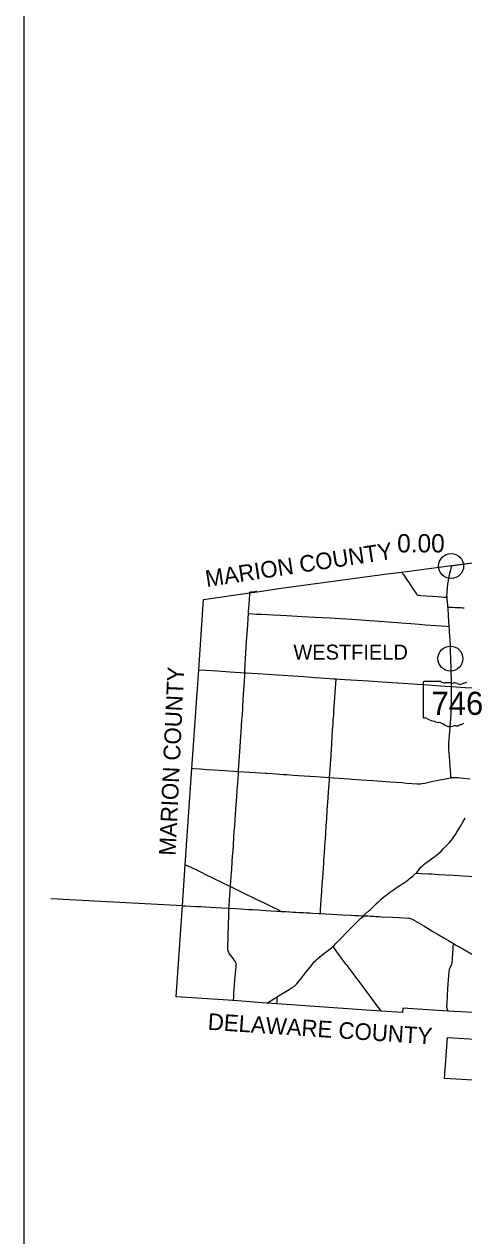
# Model space of a CAD drawing. Extents: x 1813937 to 1948437, y 826606 to 1022856.
# Drawn here: x 1813937 to 1840375, y 867056 to 939932 of the extents above; entities that cross this region are included whole.
import ezdxf

# ---------------------------------------------------------------- set-up
doc = ezdxf.new("R2010")
doc.units = 0
for name, color, linetype in [('Default', 7, 'Continuous'), ('GM_X_Adjacent_County', 7, 'Continuous'), ('GM_X_Adjacent_County_Text', 7, 'Continuous'), ('GM_X_Corporation', 7, 'Continuous'), ('GM_X_County', 7, 'Continuous'), ('GM_X_County_Road', 7, 'Continuous'), ('GM_X_State_Route', 7, 'Continuous'), ('GM_X_State_Shield', 7, 'Continuous'), ('GM_X_Township_Road', 7, 'Continuous'), ('GM_X_Township_Text', 7, 'Continuous'), ('SC_Scratch1', 7, 'Continuous')]:
    doc.layers.add(name, color=color, linetype=linetype)

msp = doc.modelspace()

# ---------------------------------------------------------------- linework, layer by layer
at = {"layer": 'Default'}
for centre in [(1839615, 907340), (1839615, 907340), (1839569, 901772)]:
    msp.add_circle(centre, 750, dxfattribs=at)
at = {"layer": 'GM_X_Adjacent_County'}
msp.add_line((1823458, 886911), (1815539, 887318), dxfattribs=at)
at = {"layer": 'GM_X_Corporation'}
msp.add_lwpolyline([(1840914, 876421), (1839212, 876522), (1839395, 878979), (1842403, 878797)], dxfattribs=at)
at = {"layer": 'GM_X_County'}
msp.add_lwpolyline([(1842150, 880416), (1839410, 880574), (1836708, 880754), (1836682, 880495), (1835395, 880574), (1829123, 881005), (1828513, 881052), (1826517, 881205), (1823082, 881429), (1823458, 886911), (1823627, 889370), (1824025, 895167), (1824431, 901093), (1824723, 905333), (1827503, 905733), (1827940, 905796), (1829401, 906007), (1835631, 906848), (1836624, 906977), (1839634, 907367), (1840896, 907530)], dxfattribs=at)
at = {"layer": 'GM_X_County_Road'}
for points in [[(1839641, 907367), (1839743, 907381), (1840149, 907433), (1840782, 907511), (1840900, 907526)], [(1836640, 906953), (1836662, 906929), (1836693, 906891), (1836740, 906824), (1836905, 906580), (1837062, 906349), (1837146, 906228), (1837275, 906038), (1837375, 905888), (1837508, 905681), (1837527, 905655), (1837538, 905643), (1837550, 905632), (1837563, 905622), (1837577, 905613), (1837592, 905607), (1837608, 905602), (1837640, 905594), (1837689, 905588), (1837786, 905579), (1838113, 905555), (1838489, 905526), (1838800, 905503), (1839012, 905486), (1839176, 905473), (1839290, 905464), (1839339, 905462), (1839367, 905462)], [(1827427, 904481), (1827436, 904614), (1827477, 905285), (1827502, 905699), (1827503, 905715), (1827505, 905729)], [(1827505, 905729), (1827509, 905742), (1827514, 905753), (1827521, 905760), (1827528, 905766), (1827537, 905772), (1827553, 905778), (1827569, 905783), (1827589, 905785), (1827635, 905791), (1827781, 905804), (1827829, 905810), (1827860, 905815), (1827876, 905820), (1827889, 905826), (1827901, 905834), (1827910, 905844)], [(1827209, 900922), (1827209, 900929), (1827211, 901011), (1827236, 901470), (1827252, 901764), (1827314, 902796), (1827379, 903779), (1827408, 904188), (1827427, 904481)], [(1839424, 904857), (1839445, 904858), (1839474, 904860), (1839506, 904861), (1839573, 904860), (1839703, 904858), (1839867, 904853), (1840015, 904847), (1840195, 904840), (1840326, 904836), (1840408, 904832)], [(1824436, 901107), (1824857, 901077), (1825561, 901032), (1826298, 900984), (1826625, 900961), (1826969, 900938), (1827209, 900922)], [(1826827, 894987), (1826827, 895001), (1826851, 895345), (1826907, 896163), (1826952, 896835), (1826990, 897375), (1827034, 898063), (1827056, 898390), (1827082, 898783), (1827090, 898914), (1827110, 899258), (1827135, 899684), (1827164, 900142), (1827200, 900716), (1827209, 900922)], [(1827209, 900922), (1827280, 900917), (1827984, 900871), (1829162, 900793), (1830734, 900688), (1831437, 900640), (1831765, 900619), (1832567, 900564), (1832693, 900555)], [(1832693, 900555), (1832927, 900540), (1833221, 900520), (1834662, 900428), (1835464, 900375), (1836413, 900311), (1837608, 900230), (1837903, 900211), (1838230, 900188), (1838983, 900135), (1839261, 900118), (1839621, 900093), (1839646, 900091)], [(1824029, 895174), (1824145, 895166), (1824536, 895137), (1824929, 895108), (1825305, 895085), (1826010, 895043), (1826550, 895005), (1826827, 894987)], [(1826343, 888063), (1826370, 888438), (1826380, 888568), (1826392, 888715), (1826419, 889075), (1826454, 889567), (1826474, 889861), (1826500, 890238), (1826520, 890532), (1826554, 891073), (1826572, 891351), (1826597, 891695), (1826625, 892087), (1826688, 892988), (1826719, 893430), (1826751, 893888), (1826777, 894264), (1826817, 894821), (1826827, 894987)], [(1826827, 894987), (1827156, 894965), (1827506, 894942)], [(1827506, 894942), (1828155, 894900), (1828455, 894881)], [(1828455, 894881), (1828532, 894877), (1828859, 894855), (1829530, 894810), (1829727, 894798), (1830120, 894771), (1830431, 894749), (1831462, 894677), (1832301, 894618)], [(1832301, 894618), (1832559, 894602), (1833475, 894538), (1833688, 894522), (1834196, 894488), (1834899, 894439), (1835177, 894417), (1835947, 894363), (1836650, 894312), (1836945, 894290), (1837567, 894246), (1837698, 894242), (1837781, 894246), (1837879, 894258), (1838024, 894284), (1838520, 894400), (1838728, 894446), (1838921, 894481), (1839196, 894528), (1839471, 894575), (1839625, 894604), (1839631, 894605)], [(1837518, 888876), (1837551, 888917), (1837744, 889159), (1837799, 889220), (1837903, 889325), (1837988, 889402), (1838065, 889464), (1838264, 889608), (1838521, 889784), (1838642, 889869), (1838731, 889941), (1838854, 890049), (1839010, 890195), (1839158, 890347), (1839507, 890717), (1839630, 890845), (1839695, 890924), (1839778, 891045), (1839879, 891194), (1839966, 891333), (1840066, 891502), (1840183, 891699), (1840348, 891983), (1840455, 892167)], [(1834737, 886671), (1834904, 886828), (1835023, 886940), (1835130, 887042), (1835261, 887166), (1835407, 887298), (1835568, 887438), (1835710, 887550), (1835908, 887695), (1836201, 887906), (1836376, 888028), (1836527, 888127), (1836707, 888242), (1836815, 888315), (1836921, 888392), (1837065, 888501), (1837181, 888592), (1837309, 888694), (1837421, 888783), (1837481, 888840), (1837518, 888876)], [(1837518, 888876), (1837545, 888874), (1837806, 888855), (1838261, 888836), (1838474, 888821), (1838867, 888795), (1839292, 888768), (1839784, 888737), (1840078, 888719), (1840275, 888709), (1840684, 888683), (1841175, 888655), (1841388, 888641), (1841830, 888620), (1842158, 888602), (1842612, 888567)], [(1826250, 886755), (1826256, 886850), (1826289, 887292), (1826303, 887521), (1826329, 887865), (1826343, 888063)], [(1826518, 881195), (1826536, 881422), (1826551, 881618), (1826574, 881929), (1826628, 882632), (1826662, 883058), (1826675, 883221), (1826686, 883334), (1826684, 883399), (1826678, 883441), (1826667, 883473), (1826659, 883494), (1826636, 883539), (1826590, 883612), (1826459, 883789), (1826348, 883931), (1826301, 883997), (1826268, 884054), (1826235, 884128), (1826207, 884204), (1826190, 884267), (1826183, 884314), (1826182, 884379), (1826191, 884592), (1826198, 884788), (1826200, 884821), (1826199, 884853), (1826200, 884902), (1826206, 885116), (1826212, 885312), (1826215, 885476), (1826221, 885735), (1826237, 886326), (1826250, 886755)], [(1826250, 886755), (1826282, 886753), (1826642, 886732), (1826970, 886714), (1827445, 886689), (1827658, 886677), (1828002, 886656), (1828461, 886630), (1829384, 886569)], [(1829384, 886569), (1829466, 886561), (1829676, 886552), (1829903, 886537), (1830116, 886527), (1830278, 886518), (1830475, 886508), (1830736, 886493), (1830931, 886483), (1831099, 886472), (1831295, 886460), (1831656, 886441), (1831744, 886436)], [(1831744, 886436), (1832062, 886419), (1832440, 886396), (1833047, 886365), (1833562, 886340), (1833797, 886327), (1834032, 886316), (1834242, 886307), (1834353, 886304)], [(1832502, 884457), (1832576, 884525), (1832678, 884631), (1832906, 884865), (1833078, 885042), (1833250, 885217), (1833397, 885371), (1833685, 885663), (1833837, 885813), (1833991, 885960), (1834109, 886073), (1834193, 886152), (1834335, 886287), (1834353, 886304)], [(1834353, 886304), (1834513, 886458), (1834678, 886615), (1834737, 886671)], [(1834353, 886304), (1834383, 886301), (1834407, 886298), (1834438, 886296), (1834628, 886291), (1834761, 886284), (1834849, 886280), (1834921, 886275)], [(1834921, 886275), (1834961, 886273), (1835065, 886268), (1835206, 886261), (1835289, 886256), (1835418, 886248), (1836089, 886214), (1836498, 886192), (1836760, 886178), (1837055, 886163), (1837120, 886156), (1837169, 886145), (1837216, 886130), (1837276, 886101), (1837967, 885691), (1838515, 885365), (1838829, 885180), (1839168, 884983), (1839465, 884807), (1839753, 884634)], [(1829163, 881447), (1829223, 881484), (1829868, 881877), (1830063, 881997), (1830187, 882077), (1830227, 882105), (1830275, 882149), (1830330, 882209), (1830475, 882386), (1830710, 882682), (1830923, 882952), (1831137, 883222), (1831331, 883466), (1831406, 883553), (1831475, 883623), (1831560, 883701), (1831700, 883815), (1831942, 884008), (1832417, 884385), (1832502, 884457)], [(1839429, 880574), (1839381, 880732), (1839365, 880796), (1839361, 880827), (1839361, 880876), (1839370, 881056), (1839423, 881923), (1839457, 882480), (1839475, 882709), (1839502, 882953), (1839513, 883035), (1839518, 883070), (1839526, 883110), (1839539, 883145), (1839552, 883173), (1839636, 883353), (1839660, 883414), (1839673, 883462), (1839684, 883527), (1839693, 883658), (1839721, 884067), (1839736, 884312), (1839746, 884506), (1839751, 884583), (1839753, 884634)], [(1839753, 884634), (1839900, 884546), (1840313, 884307), (1841735, 883496), (1842075, 883304), (1842113, 883283), (1842148, 883267), (1842176, 883258), (1842206, 883252), (1842265, 883243), (1842304, 883240), (1842349, 883237)], [(1828526, 881056), (1828986, 881338), (1829163, 881447)]]:
    msp.add_lwpolyline(points, dxfattribs=at)
at = {"layer": 'GM_X_State_Route'}
for points in [[(1839619, 894616), (1839616, 894620), (1839611, 894630), (1839608, 894643), (1839606, 894660), (1839600, 894774), (1839578, 895052), (1839536, 895559), (1839509, 895902), (1839492, 896115), (1839481, 896262), (1839474, 896409), (1839471, 896524), (1839473, 896606), (1839477, 896688), (1839495, 896901), (1839518, 897146), (1839541, 897407), (1839564, 897668), (1839577, 897848), (1839599, 898192), (1839616, 898470), (1839625, 898634), (1839635, 898896), (1839639, 899093), (1839642, 899306), (1839645, 899552), (1839646, 899879), (1839647, 900076), (1839646, 900091), (1839642, 900273), (1839638, 900437), (1839630, 900666), (1839624, 900879), (1839617, 901092), (1839611, 901305), (1839601, 901617), (1839594, 901797), (1839583, 902158), (1839577, 902371), (1839569, 902600), (1839553, 902944), (1839541, 903140), (1839526, 903369), (1839508, 903631), (1839503, 903706), (1839481, 904024), (1839459, 904367), (1839449, 904514), (1839438, 904662), (1839428, 904809), (1839424, 904857), (1839420, 904907), (1839407, 905037), (1839395, 905151), (1839374, 905363), (1839367, 905462), (1839367, 905469), (1839364, 905527), (1839365, 905610), (1839368, 905692), (1839375, 905790), (1839394, 906002), (1839421, 906263), (1839434, 906361), (1839453, 906474), (1839478, 906603), (1839525, 906828), (1839589, 907116), (1839629, 907309), (1839641, 907367)], [(1840732, 894516), (1840357, 894561), (1840162, 894586), (1840032, 894601), (1839967, 894607), (1839902, 894609), (1839836, 894607), (1839672, 894597), (1839660, 894597), (1839648, 894599), (1839638, 894601), (1839631, 894605), (1839623, 894611), (1839619, 894616)]]:
    msp.add_lwpolyline(points, dxfattribs=at)
at = {"layer": 'GM_X_State_Shield'}
for p, q in [((1837940, 900352), (1837940, 898239)), ((1838994, 900388), (1837974, 900388))]:
    msp.add_line(p, q, dxfattribs=at)
for centre, major_axis, start_param, end_param in [((1837980, 900357), (40.3, 0), 1.712693, 3.28349), ((1839236, 900634), (391, 0), 4.042523, 4.731795), ((1839366, 899202), (1404, 0), 1.404758, 1.657858), ((1839685, 900367), (113, 0), 3.836095, 5.185415), ((1839850, 900123), (235, 0), 0.950623, 2.079405), ((1840153, 900458), (282, 0), 4.081561, 5.145723), ((1840651, 899743), (743, 0), 1.699011, 2.107814), ((1837980, 898234), (40.7, 0), 3.00124, 4.508301), ((1837986, 898450), (310, 0), 4.665946, 4.897461), ((1838050, 898117), (112, 0), 0.519207, 1.627899), ((1839463, 900016), (2665, 0), 4.195997, 4.488961), ((1838668, 897289), (834, 0), 0.823519, 1.323587), ((1840136, 898034), (298, 0), 4.937069, 5.64225), ((1839570, 898106), (529, 0), 4.026481, 4.996735), ((1839876, 897376), (435, 0), 1.495662, 1.94098), ((1839915, 897948), (282, 0), 4.691044, 5.507374), ((1840170, 897743), (79.4, 0), 1.147584, 2.315152)]:
    msp.add_ellipse(centre, major_axis=major_axis, ratio=0.8, start_param=start_param, end_param=end_param, dxfattribs=at)
at = {"layer": 'GM_X_Township_Road'}
for points in [[(1827427, 904481), (1827457, 904480), (1827473, 904479), (1827916, 904456), (1828195, 904442), (1828571, 904422), (1828899, 904406), (1829342, 904384), (1829735, 904363), (1830653, 904311), (1831440, 904270), (1831849, 904247), (1832341, 904219), (1832915, 904186), (1833652, 904137), (1834208, 904099), (1834700, 904064), (1835289, 904021), (1836369, 903941), (1836893, 903903), (1837188, 903880), (1837695, 903842), (1838071, 903813), (1839332, 903717), (1839463, 903709), (1839503, 903706)], [(1832301, 894618), (1832315, 894864), (1832371, 895683), (1832431, 896616), (1832465, 897124), (1832485, 897452), (1832513, 897861), (1832526, 898058), (1832553, 898418), (1832564, 898631), (1832599, 899155), (1832618, 899433), (1832657, 900006), (1832692, 900530), (1832693, 900555)], [(1839646, 900091), (1839927, 900073), (1840188, 900055), (1840467, 900036), (1840876, 900008), (1841039, 899998), (1841219, 899984), (1841332, 899976)], [(1831744, 886436), (1831748, 886478), (1831759, 886627), (1831784, 887003), (1831835, 887757), (1831862, 888166), (1831892, 888608), (1831910, 888887), (1831949, 889427), (1831968, 889689), (1831995, 890082), (1832023, 890475), (1832054, 890950), (1832073, 891245), (1832105, 891719), (1832134, 892145), (1832168, 892686), (1832197, 893112), (1832217, 893406), (1832240, 893734), (1832292, 894487), (1832301, 894618)], [(1823631, 889378), (1823874, 889262), (1824493, 888961), (1824919, 888751), (1825215, 888610), (1825334, 888554), (1825510, 888467), (1825715, 888364), (1825995, 888229), (1826321, 888074), (1826343, 888063)], [(1826343, 888063), (1826497, 887987), (1826984, 887750), (1827352, 887571), (1827617, 887441), (1827883, 887313), (1828442, 887038), (1828929, 886803), (1829195, 886675), (1829297, 886620), (1829348, 886591), (1829384, 886569)], [(1823461, 886911), (1823636, 886903), (1824259, 886869), (1824553, 886854), (1825143, 886819), (1825471, 886801), (1825864, 886779), (1826223, 886756), (1826250, 886755)], [(1835397, 880584), (1835168, 880888), (1834946, 881196), (1834743, 881474), (1834374, 881976), (1834246, 882147), (1833946, 882537), (1833673, 882885), (1833534, 883068), (1833418, 883227), (1833361, 883306), (1833304, 883382), (1833187, 883540), (1832805, 884053), (1832550, 884394), (1832520, 884433), (1832502, 884457)], [(1829130, 881016), (1829144, 881161), (1829159, 881370), (1829162, 881418), (1829163, 881447)]]:
    msp.add_lwpolyline(points, dxfattribs=at)
at = {"layer": 'SC_Scratch1'}
msp.add_lwpolyline([(1813937, 826606), (1813937, 1022856), (1948437, 1022856), (1948437, 826606)], close=True, dxfattribs=at)

# ---------------------------------------------------------------- texts
at = {"layer": 'Default'}
msp.add_text('0.00', height=1100, dxfattribs=at).set_placement((1836368, 908162))
at = {"layer": 'GM_X_Adjacent_County_Text'}
for s, rotation, p in [('MARION COUNTY', 8.68287, (1824911, 906071)), ('MARION COUNTY', 87.3751, (1823040, 889902)), ('DELAWARE COUNTY', 356.22308, (1824953, 879452))]:
    msp.add_text(s, height=1000, rotation=rotation, dxfattribs=at).set_placement(p)
at = {"layer": 'GM_X_State_Shield'}
msp.add_text('746', height=1392.2, dxfattribs=at).set_placement((1838438, 898388))
at = {"layer": 'GM_X_Township_Text'}
msp.add_text('WESTFIELD', height=900, rotation=0.00001, dxfattribs=at).set_placement((1830126, 901713))

doc.saveas('drawing.dxf')
